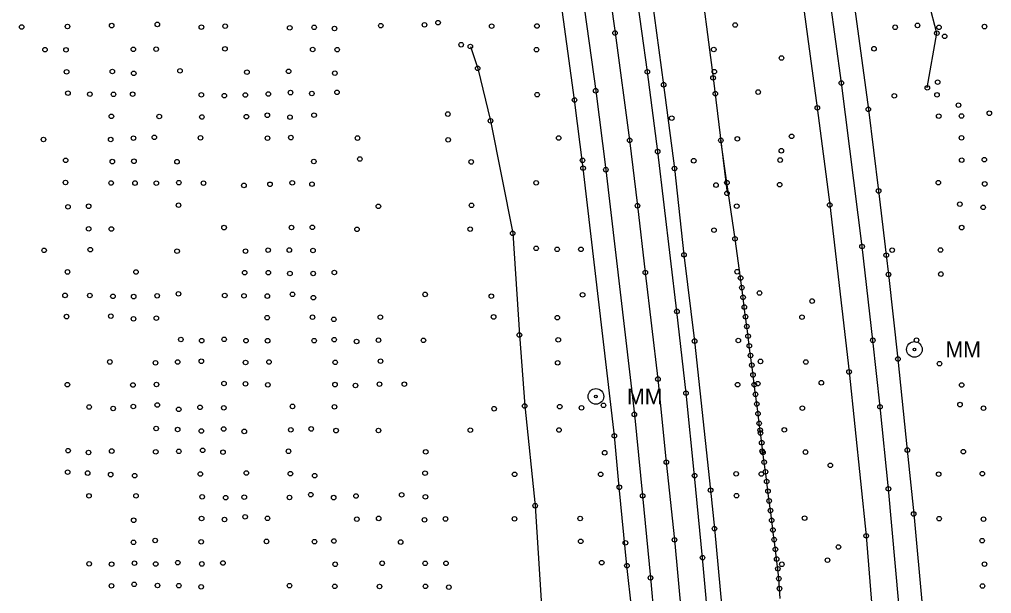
# Model space of a CAD drawing. Extents: x 20503438 to 20508873, y 7964251 to 7984667.
# Drawn here: x 20506351.9 to 20506779.9, y 7973890.2 to 7974142.9 of the extents above; entities that cross this region are included whole.
import ezdxf

# ---------------------------------------------------------------- set-up
doc = ezdxf.new("R2010")
doc.units = 0
for name, color, linetype in [('SurBreakLine', 7, 'Continuous'), ('SurDrainageArrowDown', 7, 'Continuous'), ('SurDrainageArrowUp', 7, 'Continuous'), ('SurEdgeRoadPaved', 7, 'Continuous'), ('SurEdgeShoulderPaved', 7, 'Continuous'), ('SurPointsNonDTM', 7, 'Continuous'), ('SurRoadPoints', 7, 'Continuous'), ('SurSurveyPoints', 7, 'Continuous')]:
    doc.layers.add(name, color=color, linetype=linetype)

msp = doc.modelspace()

# ---------------------------------------------------------------- linework, layer by layer
at = {"layer": 'SurBreakLine'}
for points in [[(20506693.93, 7974172.3), (20506703.16, 7974103.94), (20506708.65, 7974061.23), (20506717.15, 7973987.75), (20506724.71, 7973915.62), (20506727.66, 7973879.07), (20506730.35, 7973842.27), (20506733.65, 7973807.54), (20506740.64, 7973700.69), (20506742.76, 7973663.23), (20506744.46, 7973628.25), (20506747.41, 7973556.42), (20506749.27, 7973483.89), (20506749.75, 7973448.34), (20506750.05, 7973411.41), (20506750.05, 7973377.87), (20506750.04, 7973336.11), (20506749.88, 7973302.38), (20506749.66, 7973266.92), (20506748.75, 7973195.65), (20506748.06, 7973121.35), (20506742.68, 7972730.78)], [(20506610.16, 7974165.22), (20506614.11, 7974136.91), (20506620.53, 7974089.67), (20506623.97, 7974060.88), (20506627.43, 7974031.51), (20506632.99, 7973984.59), (20506636.68, 7973948.05), (20506640.32, 7973913.84), (20506646.44, 7973846.7), (20506649.44, 7973809.9), (20506652.64, 7973765.48), (20506654.43, 7973739.41), (20506658.64, 7973666.41), (20506660.5, 7973630.6)]]:
    msp.add_lwpolyline(points, dxfattribs=at)
at = {"layer": 'SurDrainageArrowDown'}
for points in [[(20506751.61, 7974112.75), (20506755.78, 7974136.83), (20506752.41, 7974149.78)], [(20506550.42, 7974130.95), (20506553.64, 7974121.34), (20506559.29, 7974098.23), (20506569.05, 7974048.75), (20506572, 7974004), (20506574.33, 7973972.77), (20506578.92, 7973928.84), (20506582.26, 7973875.6), (20506586.51, 7973846.62), (20506588.21, 7973801.26), (20506587.58, 7973756.81), (20506589.42, 7973702.56), (20506588.88, 7973653.25), (20506585.8, 7973578.22)], [(20506686.87, 7973888.01), (20506686.54, 7973892.39), (20506686.21, 7973896.77), (20506685.81, 7973901.11), (20506685.27, 7973905.38), (20506684.72, 7973909.65), (20506684.17, 7973913.91), (20506683.62, 7973918.18), (20506683.08, 7973922.44), (20506682.53, 7973926.71), (20506681.98, 7973930.97), (20506681.44, 7973935.24), (20506680.89, 7973939.51), (20506680.34, 7973943.77), (20506679.79, 7973948.04), (20506679.25, 7973952.3), (20506678.7, 7973956.57), (20506678.15, 7973960.84), (20506677.6, 7973965.1), (20506677.06, 7973969.37), (20506676.51, 7973973.63), (20506675.96, 7973977.9), (20506675.41, 7973982.16), (20506674.87, 7973986.43), (20506674.32, 7973990.7), (20506673.77, 7973994.96), (20506673.22, 7973999.23), (20506672.68, 7974003.49), (20506672.13, 7974007.76), (20506671.58, 7974012.03), (20506671.03, 7974016.29), (20506670.49, 7974020.56), (20506669.94, 7974024.82), (20506669.39, 7974029.09), (20506666.93, 7974046.32), (20506663.37, 7974071.06), (20506660.69, 7974089.69)]]:
    msp.add_lwpolyline(points, dxfattribs=at)
at = {"layer": 'SurDrainageArrowUp'}
msp.add_lwpolyline([(20506621.79, 7974294.22), (20506624.96, 7974291.77), (20506628.95, 7974291.01), (20506631.32, 7974289.89), (20506631.38, 7974288.67), (20506633.11, 7974281.11), (20506635.15, 7974272.15), (20506637.66, 7974254.12), (20506638.18, 7974250.44), (20506642.45, 7974222.54), (20506646.18, 7974196.79), (20506646.4, 7974195.46), (20506650.69, 7974167.8), (20506657.28, 7974117.15), (20506663.41, 7974066.36)], dxfattribs=at)
at = {"layer": 'SurEdgeRoadPaved'}
for points in [[(20506716.24, 7974173.38), (20506725.64, 7974103.3), (20506730.15, 7974067.41), (20506733.52, 7974039.13), (20506734.53, 7974030.65), (20506738.66, 7973993.41), (20506742.8, 7973953.35), (20506745.6, 7973925.24), (20506749.55, 7973883.47), (20506752.19, 7973850.05), (20506755.45, 7973811.55), (20506757.36, 7973783.27), (20506759.35, 7973755.11), (20506760.57, 7973738.24), (20506762.7, 7973701.3), (20506766.3, 7973628.52)], [(20506639.45, 7973610.26), (20506637.61, 7973650.43), (20506636.17, 7973677.06), (20506634.34, 7973710.01), (20506633.41, 7973724.63), (20506631.92, 7973747.73), (20506628.72, 7973796.13), (20506623.96, 7973852.37), (20506622.71, 7973871.72), (20506621.49, 7973882.9), (20506619.34, 7973902.48), (20506615.99, 7973936.99), (20506613.82, 7973959.6), (20506600.04, 7974077.44), (20506596.29, 7974107.44), (20506588.06, 7974167.58)], [(20506674, 7973590.15), (20506670.75, 7973659.42), (20506668.88, 7973694.23), (20506666.75, 7973729.38), (20506663.97, 7973771.29), (20506659.12, 7973834.68), (20506652.65, 7973905.99), (20506649.13, 7973942.06), (20506645.36, 7973978.38), (20506641.36, 7974014.37), (20506632.9, 7974084.72), (20506628.34, 7974119.83), (20506623.44, 7974155.73)], [(20506754.96, 7972745.65), (20506760.25, 7973137.58), (20506761.69, 7973282.93), (20506761.86, 7973353.9), (20506761.6, 7973424.82), (20506761.25, 7973458.85), (20506759.99, 7973532.54), (20506759.04, 7973564.75), (20506756.04, 7973636.58), (20506754.65, 7973665.96), (20506750.79, 7973733.72), (20506746.15, 7973800.82), (20506743.33, 7973835.58), (20506740.64, 7973867.92), (20506734.47, 7973936.28), (20506730.78, 7973972.39), (20506727.6, 7974001.68), (20506722.88, 7974042.92), (20506713.77, 7974114.92), (20506708.86, 7974151.42)], [(20506600.61, 7974147.04), (20506605.6, 7974111.5), (20506610.07, 7974076.73), (20506622.61, 7973969.05), (20506626.26, 7973933.24), (20506629.73, 7973897.13), (20506632.99, 7973860.8), (20506636.07, 7973823.66), (20506638.5, 7973791.32), (20506641.4, 7973753.18), (20506643.71, 7973720.83), (20506645.81, 7973683.35), (20506647.01, 7973660.24), (20506649.17, 7973617.44)]]:
    msp.add_lwpolyline(points, dxfattribs=at)
at = {"layer": 'SurEdgeShoulderPaved'}
msp.add_lwpolyline([(20506630.34, 7974152.37), (20506635.51, 7974114.13), (20506640.28, 7974077.28), (20506644.45, 7974039.3), (20506649.14, 7974001.32), (20506656.18, 7973935.68), (20506657.87, 7973918.76), (20506662.74, 7973866.45), (20506666.67, 7973820.29), (20506669.36, 7973783.88), (20506674.48, 7973709.53), (20506680.04, 7973598.16), (20506681.26, 7973562.05), (20506683.25, 7973489.61), (20506683.95, 7973452.45), (20506684.17, 7973413.27), (20506684.21, 7973379.49), (20506683.74, 7973332.17), (20506683.17, 7973234.7), (20506682.2, 7973169.26), (20506681.89, 7973143.95), (20506681.42, 7973104.97), (20506681.39, 7973102.17), (20506680.61, 7973023.61)], dxfattribs=at)
at = {"layer": 'SurPointsNonDTM'}
for centre in [(20506759.22, 7974135.43), (20506756.15, 7974115.29), (20506765.31, 7974105.13), (20506778.89, 7974101.58)]:
    msp.add_circle(centre, 1, dxfattribs=at)
at = {"layer": 'SurRoadPoints'}
for centre, radius in [((20506745.92, 7973997.64), 3.43), ((20506745.92, 7973997.64), 0.571), ((20506605.69, 7973976.95), 3.43), ((20506605.69, 7973976.95), 0.571)]:
    msp.add_circle(centre, radius, dxfattribs=at)
at = {"layer": 'SurSurveyPoints'}
for centre in [(20506412.6, 7974140.69), (20506530.22, 7974140.49), (20506536.2, 7974141.44), (20506667.01, 7974140.42), (20506747.26, 7974140.24), (20506352.87, 7974139.56), (20506373.02, 7974139.75), (20506392.48, 7974140.17), (20506431.99, 7974139.5), (20506442.46, 7974139.9), (20506470.88, 7974139.17), (20506481.65, 7974139.42), (20506490.61, 7974138.86), (20506510.96, 7974140.14), (20506559.77, 7974139.92), (20506579.72, 7974139.99), (20506614.11, 7974136.91), (20506737.44, 7974139.44), (20506755.78, 7974136.83), (20506756.77, 7974139.42), (20506776.78, 7974139.73), (20506546.38, 7974131.74), (20506363.1, 7974129.57), (20506372.35, 7974129.47), (20506402.02, 7974129.7), (20506412.09, 7974129.78), (20506442.34, 7974129.91), (20506481, 7974129.65), (20506491.79, 7974129.59), (20506550.42, 7974130.95), (20506579.54, 7974129.58), (20506657.57, 7974129.65), (20506728.11, 7974129.98), (20506687.38, 7974125.9), (20506372.63, 7974119.81), (20506392.79, 7974119.98), (20506402.2, 7974119.13), (20506422.54, 7974120.24), (20506452.03, 7974119.65), (20506470.37, 7974120.05), (20506490.73, 7974119.25), (20506553.64, 7974121.34), (20506628.34, 7974119.83), (20506657.82, 7974119.91), (20506657.28, 7974117.15), (20506713.77, 7974114.92), (20506373.22, 7974110.45), (20506471.21, 7974110.68), (20506480.61, 7974110.29), (20506491.67, 7974110.79), (20506605.6, 7974111.5), (20506635.51, 7974114.13), (20506677.12, 7974110.9), (20506751.61, 7974112.75), (20506382.89, 7974109.99), (20506393.27, 7974109.93), (20506401.71, 7974109.96), (20506431.98, 7974109.69), (20506442.08, 7974109.34), (20506451.33, 7974109.63), (20506461.46, 7974110.04), (20506579.83, 7974109.78), (20506596.29, 7974107.44), (20506658.25, 7974110.21), (20506737.08, 7974109.24), (20506755.86, 7974109.67), (20506703.16, 7974103.94), (20506725.64, 7974103.3), (20506392.37, 7974100.21), (20506413.43, 7974100.16), (20506432.2, 7974099.95), (20506451.8, 7974100.09), (20506461.01, 7974100.7), (20506471.01, 7974099.89), (20506481.6, 7974100.75), (20506540.48, 7974101.23), (20506559.29, 7974098.23), (20506639.07, 7974099.45), (20506756.64, 7974100.33), (20506766.66, 7974100.38), (20506362.44, 7974090.05), (20506392.06, 7974090.01), (20506402.06, 7974090.65), (20506411.27, 7974090.99), (20506431.58, 7974090.78), (20506461.11, 7974090.6), (20506471.39, 7974090.87), (20506500.71, 7974090.66), (20506540.63, 7974089.9), (20506589.3, 7974090.71), (20506620.53, 7974089.67), (20506660.69, 7974089.69), (20506667.98, 7974090.3), (20506691.85, 7974091.44), (20506766.65, 7974090.75), (20506632.9, 7974084.72), (20506687.33, 7974085.09), (20506372.22, 7974080.88), (20506392.77, 7974080.31), (20506402.28, 7974080.46), (20506481.47, 7974080.35), (20506501.75, 7974081.45), (20506599.8, 7974080.87), (20506648.76, 7974080.69), (20506686.81, 7974080.98), (20506766.73, 7974080.97), (20506776.7, 7974081.17), (20506421.22, 7974080.24), (20506550.79, 7974080.16), (20506600.04, 7974077.44), (20506610.07, 7974076.73), (20506640.28, 7974077.28), (20506372.17, 7974071.1), (20506392.23, 7974070.91), (20506402.76, 7974070.86), (20506412.13, 7974070.8), (20506422.03, 7974071.04), (20506432.92, 7974070.84), (20506450.71, 7974069.83), (20506462.18, 7974070.33), (20506471.99, 7974070.98), (20506480.66, 7974070.4), (20506579.37, 7974070.95), (20506658.56, 7974069.98), (20506663.37, 7974071.06), (20506686.59, 7974070.15), (20506756.46, 7974071.02), (20506776.89, 7974070.48), (20506663.41, 7974066.36), (20506730.15, 7974067.41), (20506373.27, 7974060.38), (20506382.34, 7974060.66), (20506421.93, 7974061.11), (20506509.92, 7974060.62), (20506550.9, 7974061.05), (20506623.97, 7974060.88), (20506667.69, 7974060.7), (20506708.65, 7974061.23), (20506765.91, 7974061.57), (20506776.22, 7974060.19), (20506382.37, 7974050.74), (20506392.37, 7974050.62), (20506441.97, 7974051.26), (20506471.63, 7974051.28), (20506480.85, 7974051.39), (20506500.47, 7974050.52), (20506550.35, 7974050.6), (20506766.75, 7974051.27), (20506569.05, 7974048.75), (20506657.66, 7974050.15), (20506666.93, 7974046.32), (20506579.39, 7974042.14), (20506722.88, 7974042.92), (20506362.73, 7974041.25), (20506383.05, 7974041.57), (20506421.27, 7974040.91), (20506451.43, 7974040.92), (20506461.36, 7974041.36), (20506470.7, 7974041.37), (20506481.13, 7974041.18), (20506588.63, 7974041.67), (20506599.09, 7974041.7), (20506644.45, 7974039.3), (20506733.52, 7974039.13), (20506736.11, 7974041.36), (20506757.41, 7974041.38), (20506373.05, 7974031.76), (20506403.19, 7974031.71), (20506451.04, 7974031.44), (20506461.43, 7974031.45), (20506470.96, 7974031.05), (20506481.22, 7974031.09), (20506490.53, 7974031.51), (20506627.43, 7974031.51), (20506667.87, 7974031.84), (20506669.39, 7974029.09), (20506734.53, 7974030.65), (20506757.58, 7974030.8), (20506669.94, 7974024.82), (20506371.96, 7974021.41), (20506382.84, 7974021.4), (20506393.03, 7974021.02), (20506402.19, 7974020.9), (20506412.51, 7974021.26), (20506421.88, 7974022.1), (20506442.27, 7974021.36), (20506450.75, 7974021.22), (20506461.04, 7974021.12), (20506472.1, 7974021.91), (20506481.3, 7974020.45), (20506530.48, 7974021.86), (20506559.64, 7974021.06), (20506599.82, 7974021.67), (20506670.49, 7974020.56), (20506677.71, 7974022.46), (20506671.03, 7974016.29), (20506700.88, 7974018.92), (20506372.62, 7974012.1), (20506392.13, 7974012.31), (20506510.79, 7974011.83), (20506560.64, 7974011.95), (20506641.36, 7974014.37), (20506671.58, 7974012.03), (20506696.44, 7974011.83), (20506402.11, 7974011.11), (20506412.16, 7974011.41), (20506460.94, 7974011.64), (20506480.91, 7974011.81), (20506490.3, 7974010.87), (20506588.7, 7974011.62), (20506672.13, 7974007.76), (20506572, 7974004), (20506672.68, 7974003.49), (20506422.96, 7974002), (20506432.13, 7974001.48), (20506442.03, 7974002.11), (20506451.61, 7974001.48), (20506461.13, 7974001.47), (20506481.65, 7974001.5), (20506490.47, 7974001.96), (20506500.32, 7974001.16), (20506509.96, 7974001.69), (20506529.75, 7974001.66), (20506589.11, 7974001.87), (20506649.14, 7974001.32), (20506668.38, 7974001.57), (20506673.22, 7973999.23), (20506727.6, 7974001.68), (20506746.83, 7974001.73), (20506673.77, 7973994.96), (20506391.68, 7973992.14), (20506411.77, 7973991.73), (20506421.55, 7973992.09), (20506431.93, 7973992.44), (20506451.44, 7973991.87), (20506461.76, 7973992.1), (20506490.91, 7973991.94), (20506510.87, 7973992.47), (20506588.85, 7973991.77), (20506674.32, 7973990.7), (20506678.16, 7973992.37), (20506698.13, 7973992.1), (20506738.66, 7973993.41), (20506756.96, 7973991.4), (20506674.87, 7973986.43), (20506717.15, 7973987.75), (20506372.99, 7973982.16), (20506401.83, 7973982), (20506412.19, 7973982.23), (20506441.96, 7973982.64), (20506451.41, 7973982.5), (20506461.25, 7973982.06), (20506490.83, 7973982.17), (20506510.38, 7973982.36), (20506521.35, 7973982.33), (20506632.99, 7973984.59), (20506668.07, 7973982.14), (20506675.41, 7973982.16), (20506676.95, 7973982.58), (20506704.92, 7973982.98), (20506766.75, 7973981.99), (20506499.81, 7973981.78), (20506645.36, 7973978.38), (20506675.96, 7973977.9), (20506676.51, 7973973.63), (20506766, 7973973.36), (20506382.56, 7973972.33), (20506393.15, 7973971.67), (20506402.01, 7973972.51), (20506412.55, 7973973.19), (20506422.01, 7973971.28), (20506431.41, 7973972.15), (20506441.84, 7973971.94), (20506472.08, 7973972.57), (20506490.56, 7973972.36), (20506560.86, 7973971.54), (20506574.33, 7973972.77), (20506589.77, 7973972.44), (20506599.35, 7973971.95), (20506609.03, 7973973.06), (20506622.61, 7973969.05), (20506677.06, 7973969.37), (20506696.59, 7973971.77), (20506730.78, 7973972.39), (20506776.32, 7973971.76), (20506677.6, 7973965.1), (20506412.05, 7973962.85), (20506421.51, 7973962.38), (20506431.96, 7973961.72), (20506441.78, 7973962.63), (20506450.86, 7973961.56), (20506471.34, 7973962.25), (20506480.34, 7973962.66), (20506491.29, 7973961.92), (20506509.93, 7973961.95), (20506550.39, 7973962.09), (20506589.44, 7973962.17), (20506678.04, 7973962.1), (20506678.15, 7973960.84), (20506688.63, 7973962.23), (20506613.82, 7973959.6), (20506678.7, 7973956.57), (20506373.3, 7973953.07), (20506382.3, 7973952.27), (20506392.51, 7973952.9), (20506411.89, 7973952.56), (20506422.07, 7973952.79), (20506432.55, 7973953.24), (20506441.48, 7973952.4), (20506470.32, 7973952.83), (20506530.76, 7973952.55), (20506609.57, 7973952.17), (20506678.87, 7973952.89), (20506679.25, 7973952.3), (20506697.97, 7973952.46), (20506742.8, 7973953.35), (20506767.44, 7973952.63), (20506636.68, 7973948.05), (20506679.79, 7973948.04), (20506373.09, 7973943.64), (20506680.34, 7973943.77), (20506708.91, 7973946.61), (20506381.93, 7973943.22), (20506392.06, 7973942.56), (20506402.58, 7973942.08), (20506431.5, 7973942.8), (20506451.76, 7973943.26), (20506471.18, 7973942.96), (20506481.88, 7973942.09), (20506530.47, 7973943.2), (20506569.88, 7973942.66), (20506607.77, 7973942.69), (20506649.13, 7973942.06), (20506667.42, 7973942.87), (20506678.53, 7973942.82), (20506680.89, 7973939.51), (20506756.59, 7973942.72), (20506775.81, 7973942.96), (20506615.99, 7973936.99), (20506656.18, 7973935.68), (20506681.44, 7973935.24), (20506734.47, 7973936.28), (20506382.51, 7973933.18), (20506403.17, 7973933.19), (20506432.31, 7973932.76), (20506442.67, 7973932.38), (20506450.85, 7973932.6), (20506470.79, 7973932.5), (20506480.14, 7973933.7), (20506490.23, 7973932.44), (20506500.05, 7973933.14), (20506520.16, 7973933.63), (20506530.62, 7973932.75), (20506626.26, 7973933.24), (20506667.6, 7973933.29), (20506681.98, 7973930.97), (20506578.92, 7973928.84), (20506682.53, 7973926.71), (20506402.15, 7973922.46), (20506432.07, 7973923.24), (20506442.17, 7973922.77), (20506451.23, 7973923.96), (20506461.07, 7973923.3), (20506500.44, 7973922.93), (20506510.06, 7973923.27), (20506530.22, 7973922.64), (20506539.47, 7973923.05), (20506569.85, 7973923.1), (20506598.74, 7973923.22), (20506683.08, 7973922.44), (20506697.57, 7973923.41), (20506745.6, 7973925.24), (20506756.8, 7973923.16), (20506776.35, 7973922.95), (20506657.87, 7973918.76), (20506683.62, 7973918.18), (20506411.65, 7973913.58), (20506640.32, 7973913.84), (20506684.17, 7973913.91), (20506724.71, 7973915.62), (20506775.77, 7973913.5), (20506402.09, 7973912.76), (20506431.91, 7973912.95), (20506460.67, 7973913.15), (20506481.78, 7973913.03), (20506490.32, 7973913.33), (20506519.74, 7973912.85), (20506599.01, 7973913.2), (20506618.68, 7973912.52), (20506684.72, 7973909.65), (20506712.47, 7973910.71), (20506652.65, 7973905.99), (20506685.27, 7973905.38), (20506707.64, 7973904.88), (20506382.57, 7973903.29), (20506392.44, 7973903.11), (20506402.5, 7973903.55), (20506411.88, 7973903.21), (20506421.58, 7973903.81), (20506432.19, 7973903.24), (20506441.46, 7973903.65), (20506490.91, 7973903.1), (20506511.6, 7973903.53), (20506530.53, 7973903.51), (20506539.68, 7973903.49), (20506608.26, 7973903.78), (20506619.34, 7973902.48), (20506685.81, 7973901.11), (20506687.54, 7973903.09), (20506776.76, 7973903.16), (20506629.73, 7973897.13), (20506686.21, 7973896.77), (20506392.38, 7973893.6), (20506402.4, 7973894.25), (20506412.68, 7973893.74), (20506422.03, 7973893.67), (20506431.88, 7973893.16), (20506470.76, 7973893.67), (20506490.71, 7973893.37), (20506510.43, 7973893.32), (20506530.63, 7973893.38), (20506540.93, 7973893.02), (20506686.54, 7973892.39), (20506775.92, 7973893.53)]:
    msp.add_circle(centre, 1, dxfattribs=at)

# ---------------------------------------------------------------- texts
at = {"layer": 'SurRoadPoints'}
for p in [(20506759.63, 7973994.14), (20506619.4, 7973973.45)]:
    msp.add_text('MM', height=6.995, rotation=360, dxfattribs=at).set_placement(p)

doc.saveas('drawing.dxf')
